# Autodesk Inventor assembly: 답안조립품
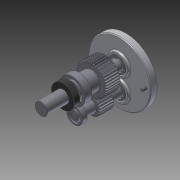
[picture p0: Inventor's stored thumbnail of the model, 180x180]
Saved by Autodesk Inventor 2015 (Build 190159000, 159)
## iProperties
Created: 2016-02
Part Number: 답안조립품
Document SubType Name: Assembly
Designer: Administrator
Author: Administrator
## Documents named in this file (10)
- C:\Users\Administrator\Desktop\460209V1005\답안조립품.iam
- C:\Users\Administrator\Desktop\460209V1005\본체.ipt
- C:\Users\Administrator\Desktop\460209V1005\커버.ipt
- C:\Users\Administrator\Desktop\460209V1005\오일실 8 22 7.ipt
- C:\Users\Administrator\Desktop\460209V1005\볼트 M4 x 10.ipt
- C:\Users\Administrator\Desktop\460209V1005\오일실 17 32 8.ipt
- C:\Users\Administrator\Desktop\460209V1005\베어링 608.ipt
- C:\Users\Administrator\Desktop\460209V1005\서브축.ipt
- C:\Users\Administrator\Desktop\460209V1005\메인축.ipt
- C:\Users\Administrator\Desktop\460209V1005\베어링 6003.ipt
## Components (2 placed, 1 different names)
1. ISO 4762 M4 x 10:1 — Insert:1
2. ISO 4762 M4 x 10:2 — Insert:2
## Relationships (2: Insert 2)
- Insert:1: ISO 4762 M4 x 10:1
- Insert:2: ISO 4762 M4 x 10:2
